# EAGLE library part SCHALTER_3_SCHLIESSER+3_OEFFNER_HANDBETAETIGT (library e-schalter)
Schalter, 3 Schließer, 3 Öffner
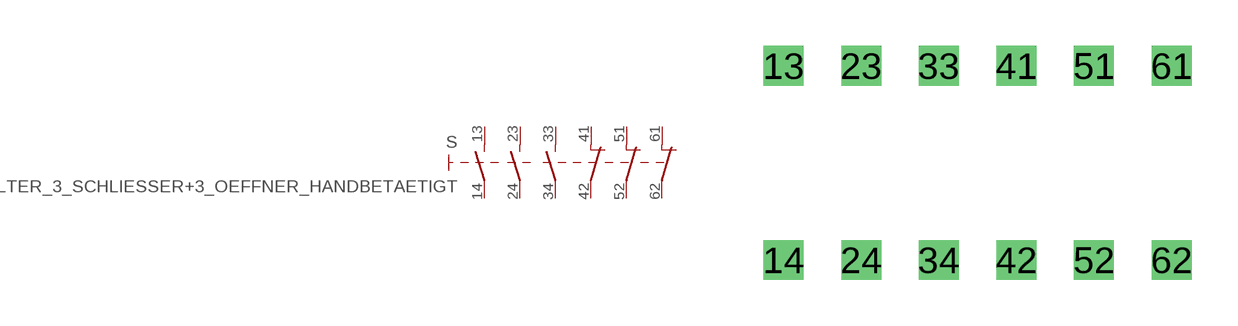
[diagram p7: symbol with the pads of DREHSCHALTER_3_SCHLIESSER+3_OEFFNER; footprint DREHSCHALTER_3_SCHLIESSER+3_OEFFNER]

Designator prefix S

## SCHALTER_3_SCHLIESSER+3_OEFFNER_HANDBETAETIGT  [DREHSCHALTER_3_SCHLIESSER+3_OEFFNER]
13  13  pas
14  14  pas
23  23  pas
24  24  pas
33  33  pas
34  34  pas
41  41  pas
42  42  pas
51  51  pas
52  52  pas
61  61  pas
62  62  pas

## Footprint DREHSCHALTER_3_SCHLIESSER+3_OEFFNER (pad centres in mm)
Dummy
drill 0.8 square: 13 -6.35,3.175; 14 -6.35,-3.175; 23 -3.81,3.175; 24 -3.81,-3.175; 33 -1.27,3.175; 34 -1.27,-3.175; 41 1.27,3.175; 42 1.27,-3.175; 51 3.81,3.175; 52 3.81,-3.175; 61 6.35,3.175; 62 6.35,-3.175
